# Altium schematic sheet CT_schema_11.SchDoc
size 281 x 153 mm
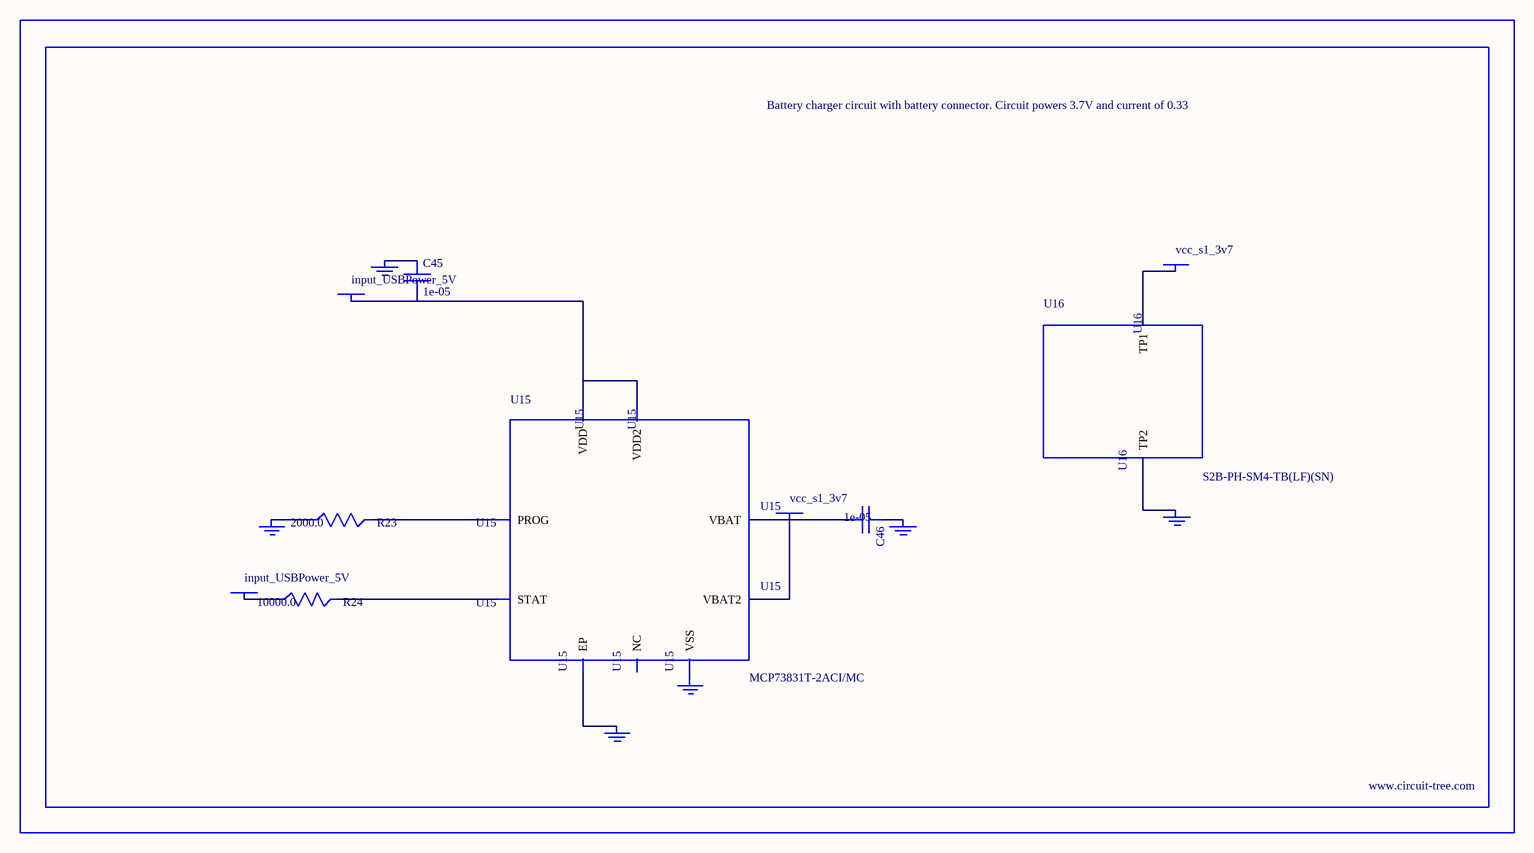
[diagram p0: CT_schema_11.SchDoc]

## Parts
BORDER10  (no value)
C45  1e-05  [C1206]
C46  1e-05  [C1206]
GND_INSTANCE_10_0  (no value)
GND_INSTANCE_10_1  (no value)
GND_INSTANCE_10_2  (no value)
GND_INSTANCE_10_3  (no value)
GND_INSTANCE_10_4  (no value)
GND_INSTANCE_10_5  (no value)
POWER_INSTANCE_10_0  input_USBPower_5V
POWER_INSTANCE_10_1  input_USBPower_5V
POWER_INSTANCE_10_2  vcc_s1_3v7
POWER_INSTANCE_10_3  vcc_s1_3v7
R23  2000.0  [R0603]
R24  10000.0  [R0603]
U15  MCP73831T-2ACI/MC  [DFN8_2X3MC]
U16  S2B-PH-SM4-TB(LF)(SN)  [JST-2-SMD]

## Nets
NetC45_1: C45.1 GND_INSTANCE_10_0.0(GND)
NetC45_2: C45.2 POWER_INSTANCE_10_0.0(PWR) U15.1(VDD) U15.2(VDD2)
NetC46_1: C46.1 GND_INSTANCE_10_1.0(GND)
NetC46_2: C46.2 POWER_INSTANCE_10_2.0(PWR) U15.3(VBAT) U15.4(VBAT2)
NetGND_INSTANCE_10_2_0: GND_INSTANCE_10_2.0(GND) R23.1
NetGND_INSTANCE_10_3_0: GND_INSTANCE_10_3.0(GND) U15.9(EP)
NetGND_INSTANCE_10_4_0: GND_INSTANCE_10_4.0(GND) U15.6(VSS)
NetGND_INSTANCE_10_5_0: GND_INSTANCE_10_5.0(GND) U16.2(TP2)
NetPOWER_INSTANCE_10_1_0: POWER_INSTANCE_10_1.0(PWR) R24.1
NetPOWER_INSTANCE_10_3_0: POWER_INSTANCE_10_3.0(PWR) U16.1(TP1)
NetR23_2: R23.2 U15.8(PROG)
NetR24_2: R24.2 U15.5(STAT)

Not connected (* = marked no-connect by the designer): U15 7(NC)

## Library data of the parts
BORDER10 = BORDER_PAGE10
C45 C46 = C1206C106K3RACTU
GND_INSTANCE_10_0-GND_INSTANCE_10_5 = GND
POWER_INSTANCE_10_0-POWER_INSTANCE_10_3 = PWR
R23 = RC0603JR-072KL
R24 = RC0603JR-0710KL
